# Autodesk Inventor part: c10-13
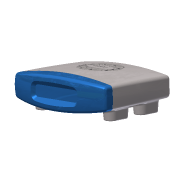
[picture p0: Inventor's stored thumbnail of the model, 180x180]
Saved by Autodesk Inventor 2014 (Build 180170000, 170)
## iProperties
Created: 2010-12
Part Number: c10-13
Material: Generic
Document SubType Name: Modeling
Designer: Thom Tremblay
Density: 1 g/cm^3
Appearance: Generic
Author: Thom Tremblay
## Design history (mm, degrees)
sketch "Sketch1"
  geometry: L1 (-60, -12)-(60, -12); L2 (60, -12)-(60, 12); L3 (60, 12)-(-60, 12); L4 (-60, 12)-(-60, -12); A1 r 350 centre (0, -332.819) between (60, 12) and (-60, 12); A2 r 350 centre (0, 332.819) between (-60, -12) and (60, -12); 3 further points
  constraints: 8 end point, 4 point on circle, 2 centre point, 2 midpoint, 2 parallel, 1 equal radius, 1 horizontal, 1 horizontal alignment, 1 perpendicular, 1 vertical alignment
  dimensions: "d0" = 120 distance of L3.end L2.end; "d1" = 24 distance of L2.end L1.end; "d2" = 350 radius of A1
workplane "Work Plane4"
sketch "Sketch5"
  geometry: L1 (-60, 12)-(-60, -12) reference; L2 (60, -12)-(60, 12) reference; L3 (-58, 10.314)-(-58, -10.314); L4 (58, -10.314)-(58, 10.314); A1 r 350 centre (0, 332.819) between (-60, -12) and (60, -12) reference; A2 r 350 centre (0, -332.819) between (60, 12) and (-60, 12) reference; A3 r 348 centre (0, 332.819) between (-58, -10.314) and (58, -10.314); A4 r 348 centre (0, -332.819) between (58, 10.314) and (-58, 10.314); 1 further point
  constraints: 4 end point, 4 point on circle, 2 centre point, 3 other
  dimensions: "d37" = 2 distance between parallel lines of L2 L4
sketch "Sketch6"
  geometry: L1 (-60, 0)-(60, 0); L2 (60, 0)-(58.843, 22.085); L3 (-60, 0)-(-58.779, 23.307); A1 r 691.758 centre (630.81, -36.204) between (-60, 0) and (-58, -100); A2 r 691.758 centre (-630.81, -36.204) between (58, -100) and (60, 0); 1 further point
  constraints: 6 end point, 4 point on circle, 2 centre point, 2 tangent, 1 horizontal
  dimensions: "d53" = 87 deg angle of L1 L3; "d54" = 87 deg angle of L1 L2 (= d53)
sketch "Sketch7"
  geometry: L1 (17.181, 0)-(12, 0) reference; L2 (15.181, -100)-(10.314, -100) reference; L3 (17.181, 0)-(16.768, 11.838); A1 r 911.322 centre (-893.585, -31.805) between (15.181, -100) and (17.181, 0); 1 further point
  constraints: 2 end point, 2 point on circle, 1 centre point, 1 tangent
  dimensions: "d56" = 88 deg angle of L1 L3
feature "LoftSrf2" sketch "Sketch5", "Sketch6", "Sketch7" dims "d57" = 0, "d58" = 90 deg, "d59" = 0, "d60" = 90 deg, "d61" = 0, "d62" = 90 deg, "d63" = 0, "d64" = 90 deg, "d65" = 0, "d66" = 90 deg
sketch "Sketch2"
  geometry: L1 (-75, -16)-(75, -16); L2 (-75, -60)-(75, -60); A1 r 183.781 centre (0, -183.781) between (75, -16) and (-75, -16); 2 further points
  constraints: 4 end point, 3 point on circle, 1 centre point, 1 coincident, 1 horizontal, 1 parallel
  dimensions: "d5" = 16 distance from line of point (0, 0) L1; "d7" = 60 distance from line of point (0, 0) L2; "d55" = 150 distance of L1.start L1.end
feature "RevolutionSrf1" sketch "Sketch2" dims angle "d8" = 40 deg
patch "Boundary Patch1" dims "d13" = 0, "d67" = 0, "d68" = 0, "d69" = 0, "d70" = 0
workplane "Work Plane1"
sketch "Sketch3"
  geometry: L1 (52, -85)-(52, -73); L2 (38, -73)-(38, -85); A1 r 7 centre (45, -73) between (52, -73) and (38, -73); A2 r 7 centre (45, -85) between (38, -85) and (52, -85); 1 further point
  constraints: 4 end point, 4 point on circle, 4 tangent, 2 centre point, 1 parallel, 1 vertical
  dimensions: "d15" = 12 distance of L1.start L1.end; "d16" = 7 radius of A1; "d50" = 45 horizontal distance of A1.centre point (0, 0); "d51" = 85 vertical distance of point (0, 0) A2.centre
extrude_surface "ExtrusionSrf2" sketch "Sketch3" dims "d19" = 14, "d20" = 5 deg
pattern_linear "Rectangular Pattern1" dims "d23" = 90
workplane "Work Plane2"
feature "Sculpt1"
sketch "Sketch4"
  geometry: L1 (-24.5, 6)-(24.5, 6); L2 (27.5, 3)-(27.5, -3); L3 (24.5, -6)-(-24.5, -6); L4 (-27.5, -3)-(-27.5, 3); A1 r 3 centre (-24.5, 3) between (-24.5, 6) and (-27.5, 3); A2 r 3 centre (24.5, 3) between (27.5, 3) and (24.5, 6); A3 r 3 centre (24.5, -3) between (24.5, -6) and (27.5, -3); A4 r 3 centre (-24.5, -3) between (-27.5, -3) and (-24.5, -6); 6 further points
  constraints: 8 end point, 8 point on circle, 8 tangent, 6 point on line, 4 centre point, 3 equal radius, 2 midpoint, 2 parallel, 1 horizontal, 1 horizontal alignment, 1 perpendicular, 1 vertical alignment
  dimensions: "d28" = 55 distance of point (27.5, -6) point (-27.5, -6); "d29" = 12 distance of point (27.5, 6) point (27.5, -6); "d30" = 3 radius of A1
extrude_surface "ExtrusionSrf6" sketch "Sketch4" dims "d31" = 14, "d32" = 45 deg
patch "Boundary Patch2" dims "d33" = 0, "d34" = 0
fillet "Fillet1" dims "d79" = 4, "d80" = 3, "d81" = 1
feature "Sculpt2"
node "Splitting Plane 1"
shell "Shell1" dims "d83" = 2
split "Split1"
  body "Solid1"
feature "Lip1" dims "d188" = 1, "d189" = 1, "d190" = 0, "d191" = 0, "d192" = 0, "d193" = 0
feature "Lip2" dims "d194" = 1, "d195" = 1, "d196" = 0, "d197" = 0, "d198" = 0, "d199" = 0.5
split "Split3"
  node "Back"
sketch "Sketch9"
  geometry: L1 (50.167, -73)-(50.167, -85) reference; L2 (39.833, -85)-(39.833, -73) reference; L3 (45, -73)-(45, -85); L4 (45, -85)-(39.833, -85); A1 r 5.167 centre (45, -73) between (50.167, -73) and (39.833, -73) reference; A2 r 5.167 centre (45, -85) between (39.833, -85) and (50.167, -85) reference; 5 further points
  constraints: 4 end point, 1 horizontal, 1 midpoint, 1 parallel, 1 perpendicular, 1 vertical, 3 other
  dimensions: "d86" = 90 distance of point (45, -79) point (-45, -79); "d89" = 40 distance of point (45, -79) point (45, -39)
  node "Projected Loop1"
feature "Boss1" dims "d92" = 0, "d93" = 0, "d94" = 7, "d95" = 2, "d96" = 0.5, "d97" = 6, "d98" = 1.25, "d99" = 3.5, "d100" = 2.5 deg, "d101" = 2.5 deg, "d102" = 2.5 deg, "d103" = 2.5 deg, "d104" = 90 deg, "d107" = 2, "d108" = 2, "d109" = 10, "d110" = 0, "d111" = 10 deg, "d112" = 2.5 deg, "d113" = 0, "d114" = 0, "d115" = 0, "d116" = 360 deg
feature "Boss2" dims "d117" = 3, "d118" = 0, "d119" = 6, "d120" = 3, "d121" = 9.5, "d122" = 2 deg, "d123" = 1 deg, "d126" = 2, "d127" = 2, "d128" = 10, "d129" = 0, "d130" = 10 deg, "d131" = 2.5 deg, "d132" = 0, "d133" = 0, "d134" = 0, "d135" = 360 deg
workplane "Work Plane6"
sketch "Sketch10"
  geometry: L1 (24, -85)-(-24, -85); L2 (-30, -79)-(-30, -51); L3 (-24, -45)-(24, -45); L4 (30, -51)-(30, -79); L5 (54.344, -100)-(-54.344, -100) reference; A1 r 6 centre (-24, -51) between (-24, -45) and (-30, -51); A2 r 6 centre (24, -51) between (30, -51) and (24, -45); A3 r 6 centre (24, -79) between (24, -85) and (30, -79); A4 r 6 centre (-24, -79) between (-30, -79) and (-24, -85); 5 further points
  constraints: 8 end point, 8 point on circle, 8 tangent, 6 point on line, 4 centre point, 3 equal radius, 2 parallel, 1 horizontal, 1 midpoint, 1 perpendicular, 1 vertical alignment
  dimensions: "d137" = 60 distance of point (-30, -45) point (30, -45); "d138" = 40 distance of point (-30, -85) point (-30, -45); "d139" = 15 distance between parallel lines of L5 L1; "d141" = 6 radius of A2
feature "Rest1" sketch "Sketch10" dims "d142" = 5, "d143" = 0, "d144" = 0, "d145" = 0, "d146" = 2 deg, "d147" = 2 deg, "d148" = 2
feature "Rule Fillet1" dims "d149" = 2, "d150" = 1
workplane "Work Plane7"
sketch "Sketch11" dims "d154" = 16, "d155" = 8, "d161" = 10, "d168" = 10
  geometry: L1 (-13, -39.858)-(-13, -90.142); L2 (-25.187, -85)-(29.449, -85); L3 (0, -39.858)-(0, -90.142); L4 (13, -39.858)-(13, -90.142); L5 (-25.187, -77)-(29.449, -77); L6 (-25.187, -69)-(29.449, -69); L7 (-25.187, -61)-(29.449, -61); L8 (-25.187, -53)-(29.449, -53); L9 (-25.187, -45)-(29.449, -45); C1 r 22.5 at (0, -65); 3 further points; 1 other entity
  constraints: 18 end point, 2 coincident, 2 vertical, 1 centre point, 1 horizontal, 1 midpoint, 1 perpendicular, 1 vertical alignment, 23 other
  dimensions: "d152" = 45 diameter of C1; "d153" = 65 distance of point (0, 0) C1.centre; "d158" = 13 distance of L1.start L3.start; "d165" = 8 distance of L2.start L5.start; "d170" = 4 distance from line of L7 point (0, -65)
feature "Grill1" sketch "Sketch11" dims "d173" = 2, "d174" = 0, "d175" = 1, "d176" = 2, "d177" = 0, "d178" = 1, "d179" = 0.5, "d180" = 0, "d181" = 2, "d182" = 1, "d183" = 2 deg, "d184" = 0, "d185" = 88.84492
sketch "Sketch12"
  geometry: L1 (-12.481, -61.203)-(12.401, -61.203); L2 (12.401, -61.203)-(12.401, -68.714); L3 (12.401, -68.714)-(-12.481, -68.714); L4 (-12.481, -68.714)-(-12.481, -61.203); 1 further point
  constraints: 2 other
emboss "Emboss1" sketch "Sketch12" dims "d186" = 0.5, "d187" = 0
sketch "Sketch13"
  geometry: L1 (0, 15.66)-(0, -14.781); 6 further points
  constraints: 2 end point, 1 coincident, 1 point on line, 1 vertical, 4 other
feature "Snap Fit1" sketch "Sketch13" dims "d200" = 4, "d201" = 2.5, "d202" = 1, "d203" = 0.9, "d204" = 10.2, "d205" = 10, "d206" = 1, "d207" = 1, "d208" = 50 deg, "d209" = 50 deg
fillet "Fillet2" dims "d213" = 2
workplane "Work Plane8"
sketch "Sketch14"
  geometry: L1 (-8.644, -6.828)-(57.644, -6.828); L2 (6.5, 3.689)-(6.5, -17.346); L3 (24.5, 3.689)-(24.5, -17.346); L4 (42.5, 3.689)-(42.5, -17.346); 2 further points
  constraints: 8 end point, 4 parallel, 2 horizontal alignment, 2 midpoint, 1 coincident, 1 horizontal, 1 perpendicular
  dimensions: "d211" = 18 distance between parallel lines of L3 L2; "d212" = 18 distance between parallel lines of L4 L3 (= d211)
feature "Rib1" sketch "Sketch14" dims "d214" = 2, "d215" = 1, "d216" = 5 deg, "d217" = 0, "d218" = 1, "d219" = 1
body "Srf2"
body "Srf3"
body "Srf4"
body "Srf5"
body "Srf6"
body "Srf7"
body "Srf8"
body "Srf9"
body "Srf11"
feature "Stitch Surface1"
body "Srf12"
extrude_surface "ExtrusionSrf3"
extrude_surface "ExtrusionSrf4"
extrude_surface "ExtrusionSrf5"
node "Front"
node "Back - Top"
node "Back - Bottom"
other parameters: "d14" = -24, "d52" = -6, "d171" = 1, "d172" = 2, "d210" = -1
